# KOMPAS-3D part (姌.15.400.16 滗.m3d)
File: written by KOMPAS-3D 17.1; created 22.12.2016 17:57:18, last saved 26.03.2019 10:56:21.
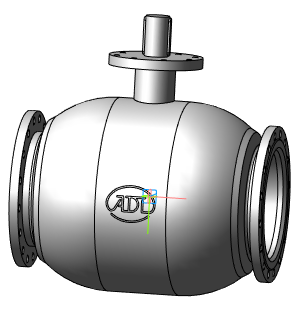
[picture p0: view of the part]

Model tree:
1. Операция без истории:3  (labels: Сталь 20  ГОСТ 1050-88)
